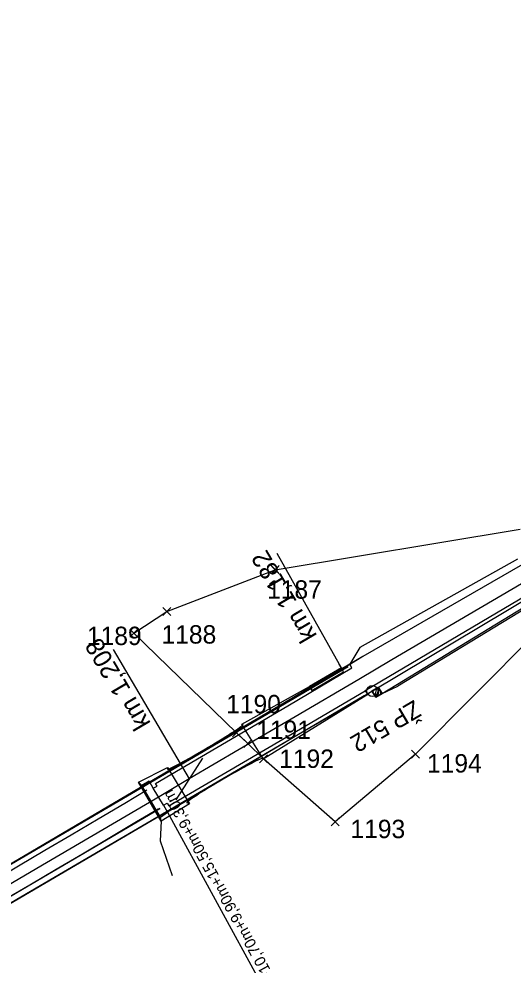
# Model space of a CAD drawing. Extents: x -738085 to -734426, y -1122197 to -1119748.
# Drawn here: x -735169.9 to -735102.7, y -1120290.8 to -1120162.2 of the extents above; entities that cross this region are included whole.
import ezdxf

# ---------------------------------------------------------------- set-up
doc = ezdxf.new("R2010")
doc.units = 0
for name, color, linetype in [('SŽDC', 7, 'Continuous'), ('Vrstva 1', 7, 'Continuous'), ('Vrstva 11', 7, 'Continuous'), ('Vrstva 12', 7, 'Continuous'), ('Vrstva 17', 7, 'Continuous'), ('Vrstva 18', 7, 'Continuous'), ('Vrstva 3', 7, 'Continuous'), ('Vrstva 36', 7, 'Continuous'), ('Vrstva 49', 7, 'Continuous'), ('Vrstva 60', 7, 'Continuous'), ('Vrstva 63', 7, 'Continuous'), ('Vrstva 9', 7, 'Continuous')]:
    doc.layers.add(name, color=color, linetype=linetype)

msp = doc.modelspace()

# ---------------------------------------------------------------- linework, layer by layer
at = {"layer": 'SŽDC'}
for p, q in [((-735135.06, -1120237.08), (-735101.77, -1120231.55)), ((-735149.78, -1120242.77), (-735135.06, -1120237.08)), ((-735095.46, -1120241.5), (-735115.98, -1120262.16)), ((-735154.27, -1120245.72), (-735149.78, -1120242.77)), ((-735140.3, -1120259.25), (-735154.27, -1120245.72)), ((-735138.78, -1120260.72), (-735140.3, -1120259.25)), ((-735136.63, -1120262.8), (-735138.78, -1120260.72)), ((-735115.98, -1120262.16), (-735126.91, -1120271.38)), ((-735126.91, -1120271.38), (-735136.63, -1120262.8))]:
    msp.add_line(p, q, dxfattribs=at)
at = {"layer": 'Vrstva 1'}
msp.add_lwpolyline([(-735048.63, -1120207.9), (-735071.26, -1120221.19), (-735095.02, -1120235.15), (-735119.18, -1120249.35), (-735123.66, -1120251.99), (-735132.32, -1120257.08), (-735139.95, -1120261.55), (-735146.73, -1120265.54), (-735150.83, -1120267.95), (-735166.13, -1120276.92), (-735184.2, -1120287.53), (-735210.89, -1120303.2), (-735238.62, -1120319.49), (-735239.7, -1120320.12), (-735247.26, -1120324.55), (-735256.8, -1120330.14), (-735273.62, -1120340.02), (-735285.77, -1120347.18), (-735296.08, -1120353.22), (-735304.06, -1120357.75)], dxfattribs=at)
msp.add_lwpolyline([(-735048.63, -1120207.9), (-735071.26, -1120221.19), (-735095.02, -1120235.15), (-735119.18, -1120249.35), (-735123.66, -1120251.99), (-735132.32, -1120257.08), (-735139.95, -1120261.55), (-735146.73, -1120265.54), (-735150.83, -1120267.95), (-735166.13, -1120276.92), (-735184.2, -1120287.53), (-735210.89, -1120303.2), (-735238.62, -1120319.49), (-735239.7, -1120320.12), (-735247.26, -1120324.55), (-735256.8, -1120330.14), (-735273.62, -1120340.02), (-735285.77, -1120347.18), (-735296.08, -1120353.22), (-735304.06, -1120357.75)], dxfattribs=at)
at = {"layer": 'Vrstva 11'}
for p, q in [((-735121.27, -1120253.25), (-735121.51, -1120254.15)), ((-735120.91, -1120253.36), (-735121.14, -1120254.24))]:
    msp.add_line(p, q, dxfattribs=at)
msp.add_circle((-735121.22, -1120253.75), 0.5, dxfattribs=at)
at = {"layer": 'Vrstva 12'}
msp.add_line((-735120.53, -1120253.93), (-735121.39, -1120254.43), dxfattribs=at)
for points in [[(-735121.9, -1120253.57), (-735121.04, -1120253.06), (-735120.53, -1120253.93), (-735121.39, -1120254.43), (-735121.9, -1120253.57)], [(-735121.04, -1120253.06), (-735120.53, -1120253.93), (-735120.53, -1120253.93)], [(-735121.9, -1120253.57), (-735121.39, -1120254.43), (-735121.39, -1120254.43)]]:
    msp.add_lwpolyline(points, dxfattribs=at)
at = {"layer": 'Vrstva 17'}
for points in [[(-735274.55, -1120337.93), (-735238.93, -1120316.99), (-735185.86, -1120285.79), (-735186.12, -1120285.36), (-735184.9, -1120284.66), (-735184.62, -1120285.09), (-735125.12, -1120250.26)], [(-735270.78, -1120340.98), (-735236.53, -1120320.93), (-735236.28, -1120321.41), (-735234.63, -1120320.42), (-735234.9, -1120319.96), (-735231.79, -1120318.14), (-735183.52, -1120289.79), (-735183.26, -1120290.18), (-735182.05, -1120289.53), (-735182.31, -1120289.06), (-735137.96, -1120263.01), (-735122.96, -1120254.17)], [(-735150.53, -1120271.29), (-735150.67, -1120273.97), (-735149.06, -1120278.68)]]:
    msp.add_lwpolyline(points, dxfattribs=at)
at = {"layer": 'Vrstva 18'}
for p, q in [((-735122.48, -1120254.04), (-735136.69, -1120262.86)), ((-735139.63, -1120258.15), (-735139.39, -1120258.15)), ((-735136.69, -1120262.86), (-735136.67, -1120262.71)), ((-735149.68, -1120263.97), (-735149.68, -1120264.2)), ((-735153.64, -1120265.99), (-735153.17, -1120266.41)), ((-735152.17, -1120265.82), (-735153.17, -1120266.41)), ((-735152.17, -1120265.82), (-735152.1, -1120265.95)), ((-735151.62, -1120266.8), (-735152.1, -1120265.95)), ((-735150.63, -1120270.71), (-735153.17, -1120266.41)), ((-735151.62, -1120266.8), (-735151.1, -1120266.51)), ((-735151.62, -1120266.8), (-735151.1, -1120266.51)), ((-735150.23, -1120269.11), (-735151.62, -1120266.8)), ((-735146.67, -1120268.9), (-735147.05, -1120268.8)), ((-735150.23, -1120269.11), (-735149.73, -1120268.82)), ((-735150.23, -1120269.11), (-735149.68, -1120270.03)), ((-735149.68, -1120270.03), (-735114.08, -1120335.34))]:
    msp.add_line(p, q, dxfattribs=at)
for points in [[(-735124.63, -1120250.42), (-735124.89, -1120249.94), (-735133.55, -1120255.07), (-735152.1, -1120265.95)], [(-735151.1, -1120266.51), (-735151.3, -1120266.16), (-735133.31, -1120255.6), (-735124.63, -1120250.42), (-735124.89, -1120249.94)], [(-735124.89, -1120249.94), (-735139.63, -1120258.15), (-735136.69, -1120262.86)], [(-735149.73, -1120268.82), (-735149.5, -1120269.19), (-735131.63, -1120258.72), (-735122.8, -1120253.54), (-735122.48, -1120254.04), (-735131.33, -1120259.18), (-735149.68, -1120270.03)], [(-735149.73, -1120268.82), (-735149.5, -1120269.19), (-735131.63, -1120258.72), (-735122.8, -1120253.54), (-735122.48, -1120254.04), (-735131.33, -1120259.18), (-735149.68, -1120270.03)], [(-735146.67, -1120268.9), (-735150.53, -1120271.29), (-735153.64, -1120265.99), (-735149.68, -1120263.97), (-735146.67, -1120268.9)], [(-735152.51, -1120267.05), (-735155.47, -1120268.89), (-735159.09, -1120271), (-735162.78, -1120273.17), (-735166.37, -1120275.27), (-735169.95, -1120277.41), (-735173.59, -1120279.55), (-735177.2, -1120281.68), (-735180.83, -1120283.75), (-735183.82, -1120285.46)], [(-735150.71, -1120269.55), (-735150.96, -1120269.62), (-735153.89, -1120271.35), (-735157.54, -1120273.56), (-735161.24, -1120275.74), (-735164.82, -1120277.83), (-735168.41, -1120279.97), (-735172.04, -1120282.11), (-735175.65, -1120284.25), (-735179.29, -1120286.31), (-735182.28, -1120288.03), (-735182.63, -1120288.29), (-735150.71, -1120269.55)], [(-735150.53, -1120271.29), (-735150.63, -1120270.71), (-735149.66, -1120270.06), (-735149.68, -1120270.03)]]:
    msp.add_lwpolyline(points, dxfattribs=at)
for centre, major_axis, ratio, start_param, end_param in [((-735144.53, -1120261.16), (5.15, 3.04), 0.040183, 3.132765, 6.191163), ((-735141.86, -1120265.75), (-5.2, -3.04), 0.050031, 3.132007, 6.311067)]:
    msp.add_ellipse(centre, major_axis=major_axis, ratio=ratio, start_param=start_param, end_param=end_param, dxfattribs=at)
at = {"layer": 'Vrstva 3'}
for p, q in [((-735157.06, -1120247.92), (-735146.73, -1120265.54)), ((-735144.91, -1120262.73), (-735148.56, -1120268.36))]:
    msp.add_line(p, q, dxfattribs=at)
at = {"layer": 'Vrstva 36'}
msp.add_lwpolyline([(-735123.16, -1120248.87), (-735124.8, -1120249.94), (-735135.02, -1120255.93), (-735143.96, -1120261.15), (-735182.98, -1120284.14), (-735184.9, -1120284.66), (-735186.12, -1120285.36), (-735187.5, -1120286.75), (-735204.22, -1120296.53), (-735238.82, -1120316.86), (-735255.42, -1120326.68), (-735274.83, -1120337.93), (-735276.42, -1120338.77)], dxfattribs=at)
at = {"layer": 'Vrstva 49'}
for p, q in [((-735071.62, -1120223.27), (-735122.8, -1120253.54)), ((-735094.31, -1120238.23), (-735118.4, -1120252.93)), ((-735120.53, -1120253.93), (-735118.4, -1120252.93)), ((-735122.8, -1120253.54), (-735122.48, -1120254.04))]:
    msp.add_line(p, q, dxfattribs=at)
for points in [[(-735120.53, -1120253.93), (-735071.24, -1120223.86), (-735031.45, -1120200.68), (-735001.39, -1120183.23), (-734979.37, -1120173.86), (-734964.99, -1120169.04), (-734946.77, -1120164.63), (-734926.51, -1120162.42), (-734904.58, -1120162.2), (-734885.6, -1120163.73), (-734860.45, -1120168.24), (-734808.17, -1120179.8), (-734802.31, -1120181.01), (-734795.9, -1120182.78), (-734795.12, -1120182.96), (-734773.64, -1120187.62), (-734748.07, -1120193.22), (-734734.64, -1120197.94), (-734724.28, -1120200.04), (-734701.99, -1120203.61), (-734701.41, -1120203.78)], [(-735093.44, -1120231.75), (-735123.16, -1120248.87), (-735124.89, -1120249.94)], [(-735102.12, -1120235.63), (-735123.55, -1120247.66), (-735124.89, -1120249.94)], [(-735122.48, -1120254.04), (-735121.9, -1120253.57), (-735121.39, -1120254.43), (-735120.53, -1120253.93)]]:
    msp.add_lwpolyline(points, dxfattribs=at)
at = {"layer": 'Vrstva 60'}
for p, q in [((-735134.61, -1120237.53), (-735135.61, -1120236.53)), ((-735134.61, -1120236.63), (-735135.61, -1120237.63)), ((-735135.51, -1120237.53), (-735134.51, -1120236.53)), ((-735135.51, -1120236.63), (-735134.51, -1120237.63)), ((-735135.06, -1120237.08), (-735135.06, -1120237.08)), ((-735149.33, -1120243.22), (-735150.33, -1120242.22)), ((-735149.33, -1120242.32), (-735150.33, -1120243.32)), ((-735150.23, -1120243.22), (-735149.23, -1120242.22)), ((-735150.23, -1120242.32), (-735149.23, -1120243.32)), ((-735149.78, -1120242.77), (-735149.78, -1120242.77)), ((-735153.82, -1120246.17), (-735154.82, -1120245.17)), ((-735153.82, -1120245.27), (-735154.82, -1120246.27)), ((-735154.72, -1120246.17), (-735153.72, -1120245.17)), ((-735154.72, -1120245.27), (-735153.72, -1120246.27)), ((-735154.27, -1120245.72), (-735154.27, -1120245.72)), ((-735139.85, -1120259.7), (-735140.85, -1120258.7)), ((-735139.85, -1120258.8), (-735140.85, -1120259.8)), ((-735140.75, -1120259.7), (-735139.75, -1120258.7)), ((-735140.75, -1120258.8), (-735139.75, -1120259.8)), ((-735140.3, -1120259.25), (-735140.3, -1120259.25)), ((-735138.33, -1120261.17), (-735139.33, -1120260.17)), ((-735138.33, -1120260.27), (-735139.33, -1120261.27)), ((-735139.23, -1120261.17), (-735138.23, -1120260.17)), ((-735139.23, -1120260.27), (-735138.23, -1120261.27)), ((-735138.78, -1120260.72), (-735138.78, -1120260.72)), ((-735136.18, -1120263.25), (-735137.18, -1120262.25)), ((-735136.18, -1120262.35), (-735137.18, -1120263.35)), ((-735137.08, -1120263.25), (-735136.08, -1120262.25)), ((-735137.08, -1120262.35), (-735136.08, -1120263.35)), ((-735115.53, -1120262.61), (-735116.53, -1120261.61)), ((-735115.53, -1120261.71), (-735116.53, -1120262.71)), ((-735116.43, -1120262.61), (-735115.43, -1120261.61)), ((-735116.43, -1120261.71), (-735115.43, -1120262.71)), ((-735115.98, -1120262.16), (-735115.98, -1120262.16)), ((-735136.63, -1120262.8), (-735136.63, -1120262.8)), ((-735126.46, -1120271.83), (-735127.46, -1120270.83)), ((-735126.46, -1120270.93), (-735127.46, -1120271.93)), ((-735127.36, -1120271.83), (-735126.36, -1120270.83)), ((-735127.36, -1120270.93), (-735126.36, -1120271.93)), ((-735126.91, -1120271.38), (-735126.91, -1120271.38))]:
    msp.add_line(p, q, dxfattribs=at)
at = {"layer": 'Vrstva 63'}
for p, q in [((-735121.84, -1120253.57), (-734977.95, -1120167.28)), ((-735310.08, -1120363.77), (-735121.84, -1120253.57)), ((-735121.8, -1120253.54), (-735121.89, -1120253.59))]:
    msp.add_line(p, q, dxfattribs=at)
msp.add_circle((-735121.84, -1120253.57), 0.756, dxfattribs=at)
at = {"layer": 'Vrstva 9'}
for p, q in [((-735125.91, -1120250.7), (-735134.76, -1120234.86)), ((-735126.06, -1120250.44), (-735130.37, -1120252.98)), ((-735126.06, -1120250.44), (-735126.37, -1120249.93)), ((-735125.76, -1120250.96), (-735126.06, -1120250.44)), ((-735130.07, -1120253.5), (-735125.76, -1120250.96)), ((-735130.37, -1120252.98), (-735130.07, -1120253.5))]:
    msp.add_line(p, q, dxfattribs=at)

# ---------------------------------------------------------------- texts
at = {"layer": 'Vrstva 18'}
msp.add_text('sv.kol.12,00m+36,00m+60,00m+12,00m vol.v.10,70m+10,70m+9,90m+15,50m+9,30m', height=1.5, rotation=118.6163, dxfattribs=at).set_placement((-735112.16, -1120334.52))
at = {"layer": 'Vrstva 3'}
msp.add_text('km 1,208', height=2.5, rotation=120.4619, dxfattribs=at).set_placement((-735151.89, -1120257.98))
at = {"layer": 'Vrstva 60'}
for s, p in [('1187', (-735136.15, -1120241.03)), ('1189', (-735160.63, -1120247.33)), ('1188', (-735150.49, -1120247.13)), ('1190', (-735141.71, -1120256.61)), ('1191', (-735137.63, -1120260.1)), ('1192', (-735134.51, -1120264.03)), ('1194', (-735114.42, -1120264.66)), ('1193', (-735124.82, -1120273.58))]:
    msp.add_text(s, height=2.5, dxfattribs=at).set_placement(p)
at = {"layer": 'Vrstva 63'}
msp.add_text('ŽP 512', height=2.4, rotation=210.4683, dxfattribs=at).set_placement((-735116.16, -1120254.73))
at = {"layer": 'Vrstva 9'}
msp.add_text('km 1,182', height=2.5, rotation=120.4838, dxfattribs=at).set_placement((-735129.29, -1120246.06))

doc.saveas('drawing.dxf')
